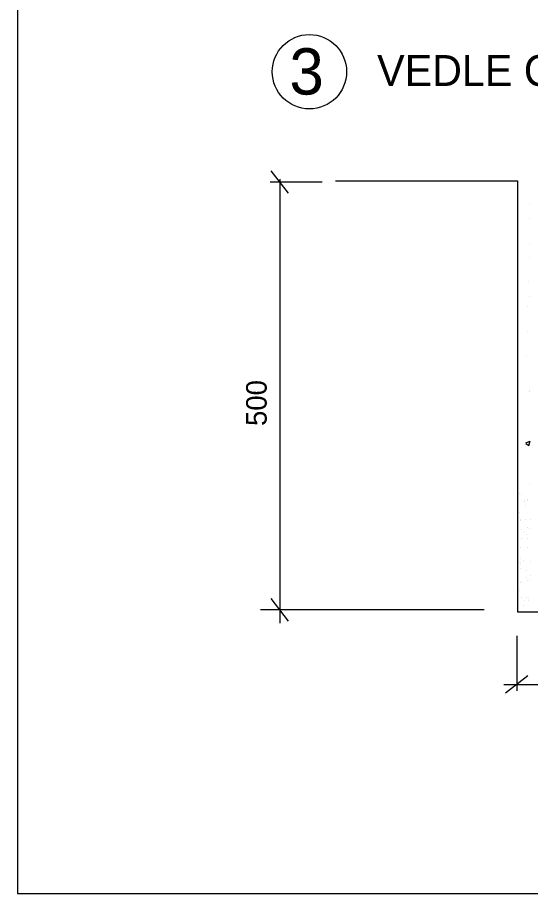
# Model space of a CAD drawing. Extents: x -480568.5 to -480543.1, y -1126945.4 to -1126930.6.
# Drawn here: x -480568.542 to -480566.047, y -1126945.416 to -1126941.158 of the extents above; entities that cross this region are included whole.
import ezdxf

# ---------------------------------------------------------------- set-up
doc = ezdxf.new("R2010")
doc.units = 0
doc.layers.add('detaily', color=7, linetype='Continuous')
doc.layers.add('ELEKTRO', color=7, linetype='Continuous')

msp = doc.modelspace()

# ---------------------------------------------------------------- linework, layer by layer
at = {"layer": 'detaily'}
for p, q in [((-480568.5418, -1126930.5663), (-480568.5418, -1126945.4163)), ((-480568.5418, -1126945.4163), (-480543.0929, -1126945.4163))]:
    msp.add_line(p, q, dxfattribs=at)
at = {"layer": 'ELEKTRO'}
for p, q in [((-480567.2236, -1126942.0125), (-480567.308, -1126941.9037)), ((-480567.0607, -1126941.9581), (-480567.3132, -1126941.9581)), ((-480567.2658, -1126941.9439), (-480567.2658, -1126944.1029)), ((-480566.9956, -1126941.9518), (-480566.1096, -1126941.9518)), ((-480566.1096, -1126941.9518), (-480566.1096, -1126944.0471)), ((-480566.0523, -1126942.0687), (-480566.0523, -1126942.0687)), ((-480566.0506, -1126942.1361), (-480566.0506, -1126942.1361)), ((-480566.0523, -1126942.256), (-480566.0523, -1126942.256)), ((-480566.0506, -1126942.3234), (-480566.0506, -1126942.3234)), ((-480566.055, -1126942.4432), (-480566.055, -1126942.4432)), ((-480566.0493, -1126942.5145), (-480566.0493, -1126942.5145)), ((-480566.0594, -1126942.563), (-480566.0594, -1126942.563)), ((-480566.0637, -1126942.6829), (-480566.0637, -1126942.6829)), ((-480566.0681, -1126942.8027), (-480566.0681, -1126942.8027)), ((-480566.0504, -1126942.9704), (-480566.0504, -1126942.9704)), ((-480566.0499, -1126942.9744), (-480566.0499, -1126942.9744)), ((-480566.0702, -1126943.2264), (-480566.0476, -1126943.2177)), ((-480566.0702, -1126943.2291), (-480566.0549, -1126943.2395)), ((-480566.0549, -1126943.2394), (-480566.0476, -1126943.2177)), ((-480566.0514, -1126943.4263), (-480566.0514, -1126943.4263)), ((-480566.0991, -1126943.4697), (-480566.0991, -1126943.4697)), ((-480566.0924, -1126943.4758), (-480566.0924, -1126943.4758)), ((-480566.0781, -1126943.5042), (-480566.0781, -1126943.5042)), ((-480566.0611, -1126943.5045), (-480566.0611, -1126943.5045)), ((-480566.0594, -1126943.5018), (-480566.0594, -1126943.5018)), ((-480566.0771, -1126943.5098), (-480566.0771, -1126943.5098)), ((-480566.0724, -1126943.5305), (-480566.0724, -1126943.5305)), ((-480566.1027, -1126943.5652), (-480566.1027, -1126943.5652)), ((-480566.0955, -1126943.6037), (-480566.0955, -1126943.6037)), ((-480566.0938, -1126943.5995), (-480566.0938, -1126943.5995)), ((-480566.0701, -1126943.5999), (-480566.0701, -1126943.5999)), ((-480566.0597, -1126943.6365), (-480566.0597, -1126943.6365)), ((-480566.0481, -1126943.6), (-480566.0481, -1126943.6)), ((-480566.0888, -1126943.6456), (-480566.0888, -1126943.6456)), ((-480566.0736, -1126943.6553), (-480566.0736, -1126943.6553)), ((-480566.0679, -1126943.6693), (-480566.0679, -1126943.6693)), ((-480566.0531, -1126943.6426), (-480566.0531, -1126943.6426)), ((-480566.1086, -1126943.6947), (-480566.1086, -1126943.6947)), ((-480566.0899, -1126943.6922), (-480566.0899, -1126943.6922)), ((-480566.0606, -1126943.6884), (-480566.0606, -1126943.6884)), ((-480566.0941, -1126943.7357), (-480566.0941, -1126943.7357)), ((-480566.0598, -1126943.7358), (-480566.0598, -1126943.7358)), ((-480566.0966, -1126943.79), (-480566.0966, -1126943.79)), ((-480566.0814, -1126943.7997), (-480566.0814, -1126943.7997)), ((-480566.0491, -1126943.801), (-480566.0491, -1126943.801)), ((-480566.1035, -1126943.8099), (-480566.1035, -1126943.8099)), ((-480566.0969, -1126943.816), (-480566.0969, -1126943.816)), ((-480566.0955, -1126943.8366), (-480566.0955, -1126943.8366)), ((-480566.0934, -1126943.8083), (-480566.0934, -1126943.8083)), ((-480566.0656, -1126943.8447), (-480566.0656, -1126943.8447)), ((-480566.0675, -1126943.8801), (-480566.0675, -1126943.8801)), ((-480566.0523, -1126943.8898), (-480566.0523, -1126943.8898)), ((-480566.0468, -1126943.8703), (-480566.0468, -1126943.8703)), ((-480566.1082, -1126943.9035), (-480566.1082, -1126943.9035)), ((-480566.0932, -1126943.906), (-480566.0932, -1126943.906)), ((-480566.0895, -1126943.901), (-480566.0895, -1126943.901)), ((-480566.0602, -1126943.8972), (-480566.0602, -1126943.8972)), ((-480566.1, -1126943.9439), (-480566.1, -1126943.9439)), ((-480566.091, -1126943.9753), (-480566.091, -1126943.9753)), ((-480566.0642, -1126943.9767), (-480566.0642, -1126943.9767)), ((-480567.2236, -1126944.0919), (-480567.308, -1126943.9831)), ((-480566.0807, -1126944.015), (-480566.0807, -1126944.015)), ((-480566.075, -1126943.9923), (-480566.075, -1126943.9923)), ((-480566.0575, -1126943.9828), (-480566.0575, -1126943.9828)), ((-480566.0563, -1126943.9899), (-480566.0563, -1126943.9899)), ((-480566.2716, -1126944.0375), (-480567.3605, -1126944.0375)), ((-480566.1096, -1126944.0471), (-480565.0549, -1126944.0471)), ((-480566.1138, -1126944.1636), (-480566.1138, -1126944.4313)), ((-480566.0594, -1126944.3576), (-480566.1682, -1126944.4421)), ((-480566.1769, -1126944.3998), (-480564.9933, -1126944.3998))]:
    msp.add_line(p, q, dxfattribs=at)
msp.add_circle((-480567.1219, -1126941.4219), 0.1806, dxfattribs=at)

# ---------------------------------------------------------------- texts
for s, height, p in [('3', 0.225, (-480567.2194, -1126941.5329)), ('VEDLE CHODNÍKU A KOMUNIKACE', 0.15, (-480566.7927, -1126941.4909))]:
    msp.add_text(s, height=height, dxfattribs=at).set_placement(p)
msp.add_text('500', height=0.1, rotation=90, dxfattribs=at).set_placement((-480567.3298, -1126943.1438))

doc.saveas('drawing.dxf')
